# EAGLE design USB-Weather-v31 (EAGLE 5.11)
SFENUM: VREG-9872

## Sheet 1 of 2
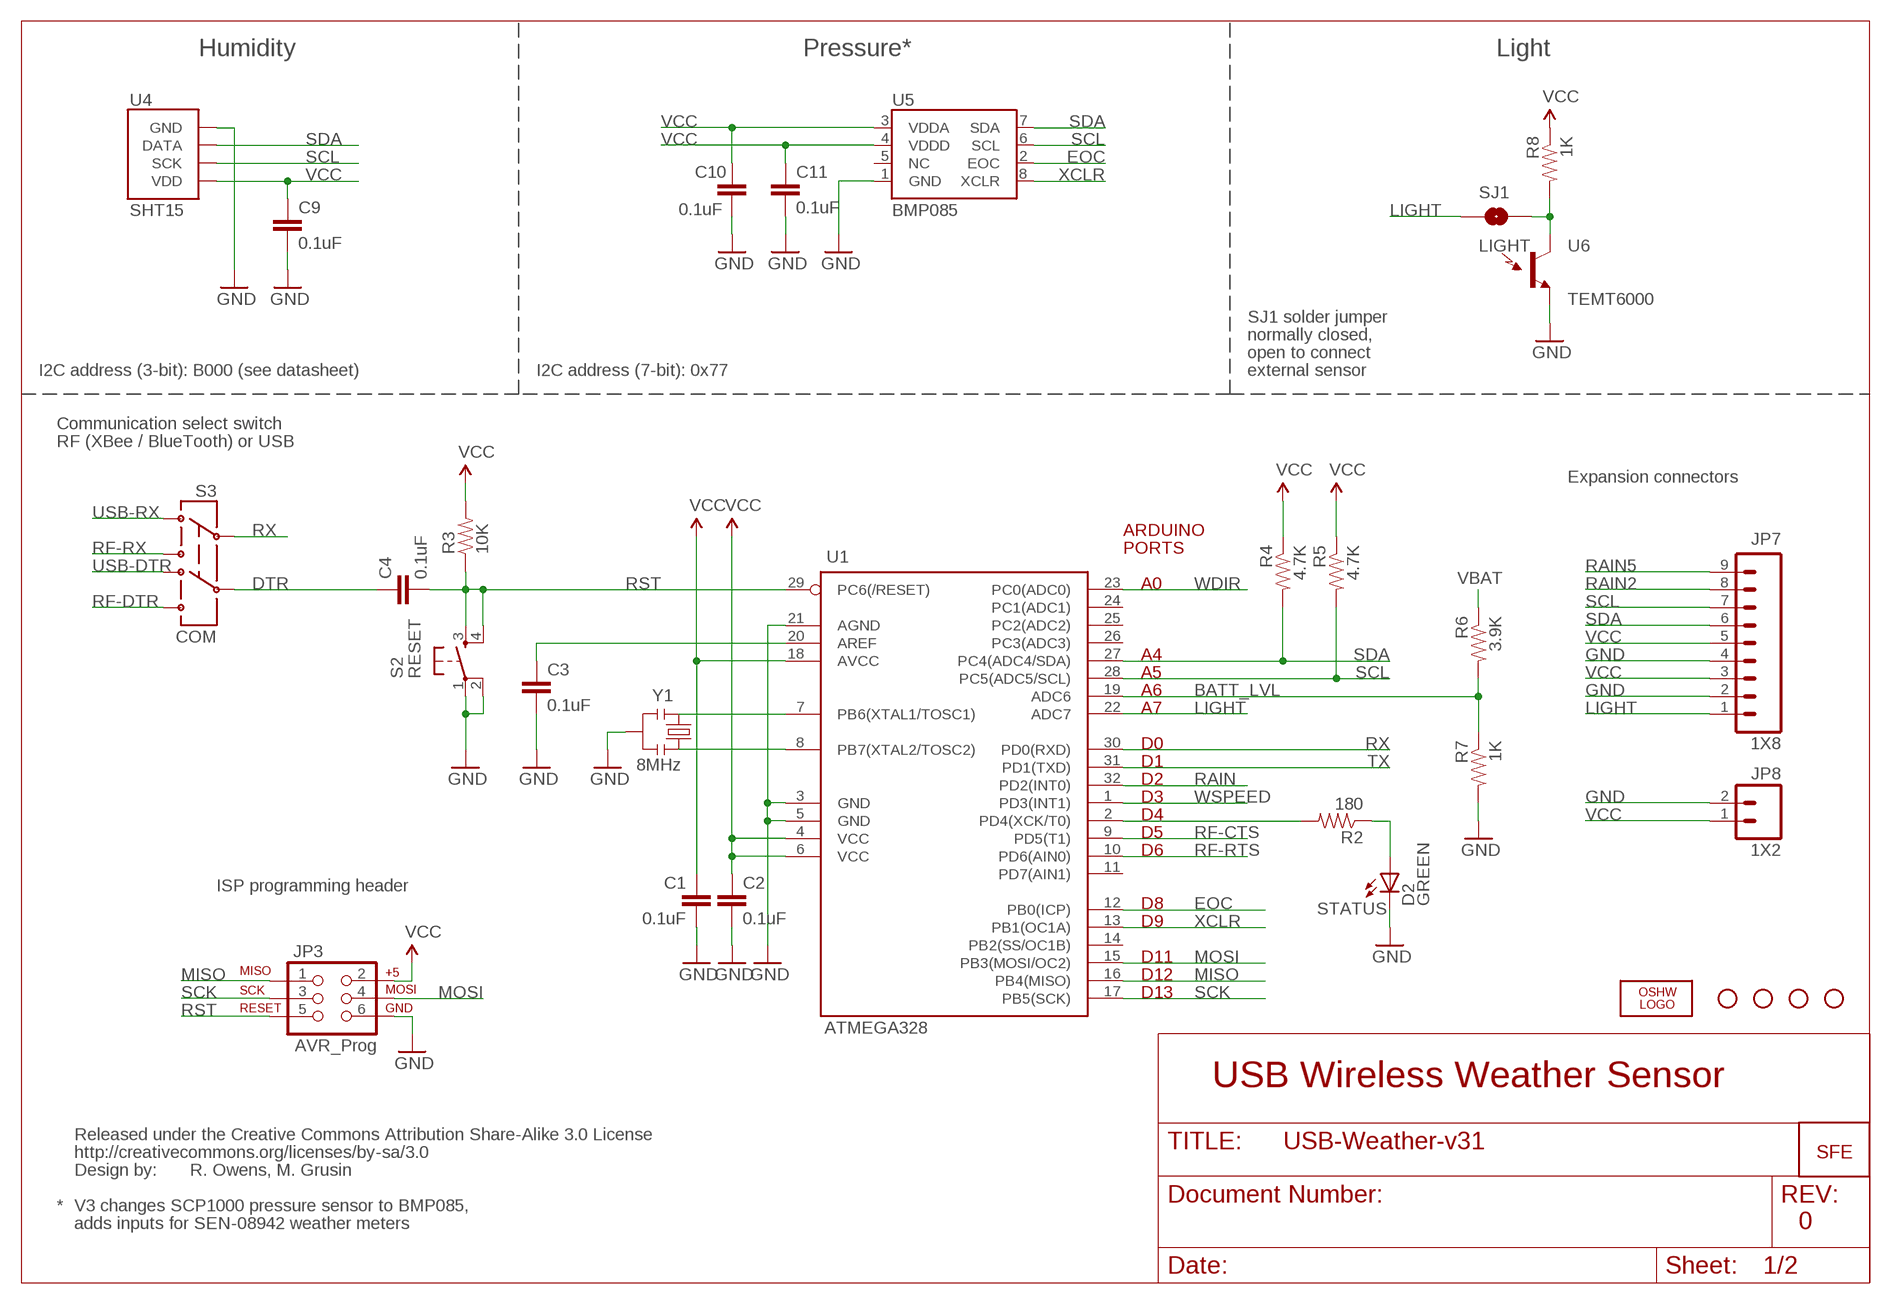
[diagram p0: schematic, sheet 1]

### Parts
C1  0.1uF  CAP0402-CAP  [0402-CAP]
C2  0.1uF  CAP0402-CAP  [0402-CAP]
C3  0.1uF  CAP0402-CAP  [0402-CAP]
C4  0.1uF  CAP0402-CAP  [0402-CAP]
C9  0.1uF  CAP0402-CAP  [0402-CAP]
C10  0.1uF  CAP0402-CAP  [0402-CAP]
C11  0.1uF  CAP0402-CAP  [0402-CAP]
D2  GREEN  LED0603  [LED-0603]
JP3  AVR_Prog  AVR_SPI_PRG_6PTH  [2X3]
JP7  1X8  M09  [1X09]
JP8  1X2  M02PTH  [1X02]
LOGO1  OSHW_LOGO_FILLX0100-NT  [OSHW_FILLX100_NOTEXT]
R2  180  RESISTOR0402-RES  [0402-RES]
R3  10K  RESISTOR0402-RES  [0402-RES]
R4  4.7K  RESISTOR0402-RES  [0402-RES]
R5  4.7K  RESISTOR0402-RES  [0402-RES]
R6  3.9K  RESISTOR0402-RES  [0402-RES]
R7  1K  RESISTOR0402-RES  [0402-RES]
R8  1K  RESISTOR0402-RES  [0402-RES]
S2  RESET  TAC_SWITCHSMD  [TACTILE_SWITCH_SMD]
S3  COM  SWITCH-DPDTSMD  [AYZ0202]
SJ1  LIGHT  SOLDERJUMPERNC  [SJ_2S]
U1  ATMEGA328  AVR-MEGA8-AI  [TQFP32-08]
U4  SHT15  SHT1XSMD  [SHT1X]
U5  BMP085  [BMP085]
U6  TEMT6000  [TEMT6000-SEN]
U$1  LOGO-SFENEW  [SFE-NEW-WEBLOGO]
U$2  STAND-OFF  [STAND-OFF]
U$3  STAND-OFF  [STAND-OFF]
U$4  STAND-OFF  [STAND-OFF]
U$5  STAND-OFF  [STAND-OFF]
U$6  CREATIVE_COMMONS  [CREATIVE_COMMONS]
Y1  8MHz  RESONATORSMD  [RESONATOR-SMD]

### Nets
BATT_LVL: R6.2 R7.1 U1.19(ADC6)
DTR: C4.1 S3.5
EOC: U1.12(PB0(ICP)) U5.2(EOC)
GND: C1.2 C2.2 C3.2 C9.2 C10.1 C11.2 D2.C JP3.6 JP7.2 JP7.4 JP8.2 R7.2 S2.1 S2.2 U1.3(GND) U1.5(GND) U1.21(AGND) U4.1(GND) U5.1(GND) U6.EMITTER(E1) Y1.2 ; also sheet 2
LIGHT: JP7.1 SJ1.1 U1.22(ADC7)
MISO: JP3.1 U1.16(PB4(MISO))
MOSI: JP3.4 U1.15(PB3(MOSI/OC2))
N$4: R2.2 U1.2(PD4(XCK/T0))
N$5: D2.A R2.1
N$8: C3.1 U1.20(AREF)
N$9: R8.2 SJ1.2 U6.COLLECTOR(C1)
N$10: U1.7(PB6(XTAL1/TOSC1)) Y1.1
N$14: U1.8(PB7(XTAL2/TOSC2)) Y1.3
RAIN: U1.32(PD2(INT0)) ; also sheet 2
RAIN2: JP7.8 ; also sheet 2
RAIN5: JP7.9 ; also sheet 2
RF-CTS: U1.9(PD5(T1)) ; also sheet 2
RF-DTR: S3.6 ; also sheet 2
RF-RTS: U1.10(PD6(AIN0)) ; also sheet 2
RF-RX: S3.3 ; also sheet 2
RST: C4.2 JP3.5 R3.1 S2.3 S2.4 U1.29(PC6(/RESET))
RX: S3.2 U1.30(PD0(RXD))
SCK: JP3.3 U1.17(PB5(SCK))
SCL: JP7.7 R5.2 U1.28(PC5(ADC5/SCL)) U4.3(SCK) U5.6(SCL)
SDA: JP7.6 R4.2 U1.27(PC4(ADC4/SDA)) U4.2(DATA) U5.7(SDA)
TX: U1.31(PD1(TXD)) ; also sheet 2
USB-DTR: S3.4 ; also sheet 2
USB-RX: S3.1 ; also sheet 2
VBAT: R6.1 ; also sheet 2
VCC: C1.1 C2.1 C9.1 C10.2 C11.1 JP3.2 JP7.3 JP7.5 JP8.1 R3.2 R4.1 R5.1 R8.1 U1.4(VCC) U1.6(VCC) U1.18(AVCC) U4.4(VDD) U5.3(VDDA) U5.4(VDDD) ; also sheet 2
WDIR: U1.23(PC0(ADC0)) ; also sheet 2
WSPEED: U1.1(PD3(INT1)) ; also sheet 2
XCLR: U1.13(PB1(OC1A)) U5.8(XCLR)
Unconnected: U1.11(PD7(AIN1)) U1.14(PB2(SS/OC1B)) U1.24(PC1(ADC1)) U1.25(PC2(ADC2)) U1.26(PC3(ADC3)) U5.5(NC)

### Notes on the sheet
- Humidity | Pressure* | Light
- SJ1 solder jumper
- normally closed,
- open to connect
- I2C address (3-bit): B000 (see datasheet) | I2C address (7-bit): 0x77 | external sensor
- Communication select switch
- RF (XBee / BlueTooth) or USB
- Expansion connectors
- ARDUINO
- PORTS
- A0
- A4
- A5
- A6
- A7
- D0
- D1
- D2
- D3
- D4
- D5
- D6
- ISP programming header
- D8
- STATUS
- D9
- D11
- D12
- D13
- USB Wireless Weather Sensor
- R. Owens, M. Grusin
- * | V3 changes SCP1000 pressure sensor to BMP085,
- adds inputs for SEN-08942 weather meters | 0

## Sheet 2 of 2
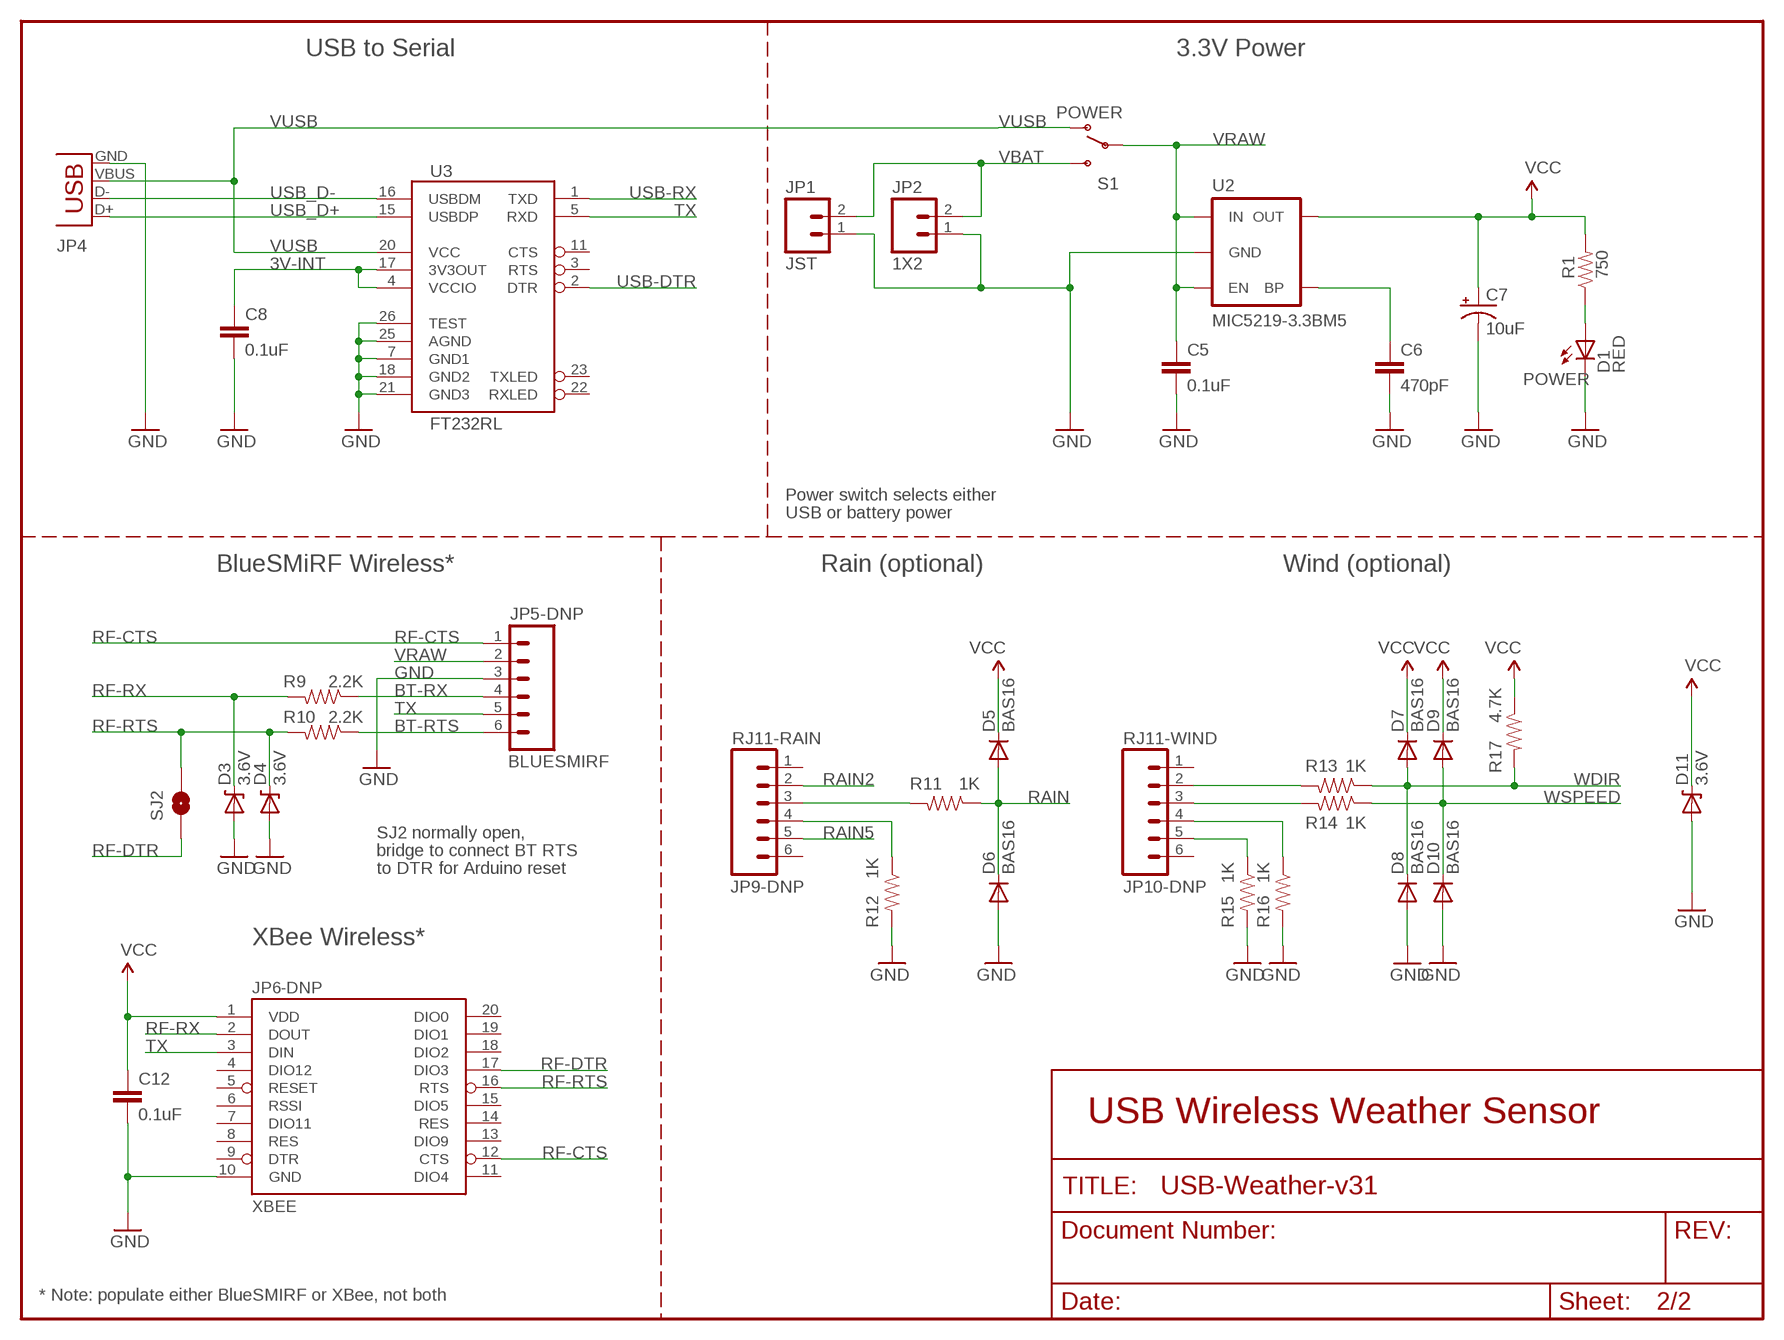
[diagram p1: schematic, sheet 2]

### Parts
C5  0.1uF  CAP0402-CAP  [0402-CAP]
C6  470pF  CAP0402-CAP  [0402-CAP]
C7  10uF  CAP_POL1206  [EIA3216]
C8  0.1uF  CAP0402-CAP  [0402-CAP]
C12  0.1uF  CAP0402-CAP  [0402-CAP]
D1  RED  LED0603  [LED-0603]
D3  3.6V  DIODE-ZENER-BZT52  [SOD-323]
D4  3.6V  DIODE-ZENER-BZT52  [SOD-323]
D5  BAS16  DIODESOD  [SOD-323]
D6  BAS16  DIODESOD  [SOD-323]
D7  BAS16  DIODESOD  [SOD-323]
D8  BAS16  DIODESOD  [SOD-323]
D9  BAS16  DIODESOD  [SOD-323]
D10  BAS16  DIODESOD  [SOD-323]
D11  3.6V  DIODE-ZENER-BZT52  [SOD-323]
JP1  JST  M02-JST-2MM-SMT  [JST-2-SMD]
JP2  1X2  M021X02_NO_SILK  [1X02_NO_SILK]
JP4  USBSMD  [USB-MINIB]
JP5-DNP  BLUESMIRF  M06SIP  [1X06]
JP6-DNP  XBEE  XBEE-1B1  [XBEE-1]
JP9-DNP  RJ11-RAIN  RJ11-6PTH  [RJ11-6]
JP10-DNP  RJ11-WIND  RJ11-6PTH  [RJ11-6]
R1  750  RESISTOR0402-RES  [0402-RES]
R9  2.2K  RESISTOR0402-RES  [0402-RES]
R10  2.2K  RESISTOR0402-RES  [0402-RES]
R11  1K  RESISTOR0402-RES  [0402-RES]
R12  1K  RESISTOR0402-RES  [0402-RES]
R13  1K  RESISTOR0402-RES  [0402-RES]
R14  1K  RESISTOR0402-RES  [0402-RES]
R15  1K  RESISTOR0402-RES  [0402-RES]
R16  1K  RESISTOR0402-RES  [0402-RES]
R17  4.7K  RESISTOR0402-RES  [0402-RES]
S1  POWER  SWITCH-SPSTSMD  [AYZ0202]
SJ2  SOLDERJUMPERNO  [SJ_2S-NO]
U2  MIC5219-3.3BM5  V_REG_LDOSMD  [SOT23-5]
U3  FT232RL  FT232RL-BASICSSOP  [SSOP28DB]

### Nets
3V-INT: C8.1 U3.4(VCCIO) U3.17(3V3OUT)
BT-RTS: JP5-DNP.6 R10.1
BT-RX: JP5-DNP.4 R9.1
GND: C5.2 C6.2 C7.C(-) C8.2 C12.2 D1.C D3.2(A) D4.2(A) D6.2(A) D8.2(A) D10.2(A) D11.2(A) JP1.1 JP2.1 JP4.GND JP5-DNP.3 JP6-DNP.10(GND) R12.2 R15.2 R16.2 U2.2(GND) U3.7(GND1) U3.18(GND2) U3.21(GND3) U3.25(AGND) U3.26(TEST) ; also sheet 1
N$1: D1.A R1.1
N$2: JP10-DNP.2 R13.2
N$3: JP10-DNP.3 R14.2
N$6: C6.1 U2.4(BP)
N$7: JP9-DNP.3 R11.2
N$11: JP9-DNP.4 R12.1
N$12: JP10-DNP.5 R15.1
N$13: JP10-DNP.4 R16.1
RAIN: D5.2(A) D6.1(C) R11.1 ; also sheet 1
RAIN2: JP9-DNP.2 ; also sheet 1
RAIN5: JP9-DNP.5 ; also sheet 1
RF-CTS: JP5-DNP.1 JP6-DNP.12(CTS) ; also sheet 1
RF-DTR: JP6-DNP.17(DIO3) SJ2.1 ; also sheet 1
RF-RTS: D4.1(C) JP6-DNP.16(RTS) R10.2 SJ2.2 ; also sheet 1
RF-RX: D3.1(C) JP6-DNP.2(DOUT) R9.2 ; also sheet 1
TX: JP5-DNP.5 JP6-DNP.3(DIN) U3.5(RXD) ; also sheet 1
USB-DTR: U3.2(DTR) ; also sheet 1
USB-RX: U3.1(TXD) ; also sheet 1
USB_D+: JP4.D+ U3.15(USBDP)
USB_D-: JP4.D- U3.16(USBDM)
VBAT: JP1.2 JP2.2 S1.3(S) ; also sheet 1
VCC: C7.A(+) C12.1 D5.1(C) D7.1(C) D9.1(C) D11.1(C) JP6-DNP.1(VDD) R1.2 R17.1 U2.5(OUT) ; also sheet 1
VRAW: C5.1 JP5-DNP.2 S1.2(P) U2.1(IN) U2.3(EN)
VUSB: JP4.VBUS S1.1(O) U3.20(VCC)
WDIR: D7.2(A) D8.1(C) R13.1 R17.2 ; also sheet 1
WSPEED: D9.2(A) D10.1(C) R14.1 ; also sheet 1
Unconnected: JP6-DNP.4(DIO12) JP6-DNP.5(RESET) JP6-DNP.6(RSSI) JP6-DNP.7(DIO11) JP6-DNP.8(RES) JP6-DNP.9(DTR) JP6-DNP.11(DIO4) JP6-DNP.13(DIO9) JP6-DNP.14(RES) JP6-DNP.15(DIO5) JP6-DNP.18(DIO2) JP6-DNP.19(DIO1) JP6-DNP.20(DIO0) JP9-DNP.1 JP9-DNP.6 JP10-DNP.1 JP10-DNP.6 U3.3(RTS) U3.11(CTS) U3.22(RXLED) U3.23(TXLED)

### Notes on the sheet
- USB to Serial | 3.3V Power
- JP4
- POWER
- Power switch selects either
- USB or battery power
- Rain (optional) | Wind (optional)
- BlueSMiRF Wireless*
- SJ2 normally open,
- bridge to connect BT RTS
- to DTR for Arduino reset
- XBee Wireless*
- USB Wireless Weather Sensor
- * Note: populate either BlueSMIRF or XBee, not both

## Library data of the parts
C1-C6 C8-C12 = SparkFun:CAP: Capacitor
C7 = SparkFun:CAP_POL: Capacitor Polarized
D1 D2 = SparkFun:LED: LEDs
D3 D4 D11 = SparkFun:DIODE-ZENER: Zener Diode
D5-D10 = SparkFun:DIODE: Diode
JP1 JP2 JP8 = SparkFun:M02: Header 2
JP3 = SparkFun:AVR_SPI_PRG_6: AVR ISP 6 Pin This is the reduced ISP connector for AVR programming. Common on Arduino. This footprint will take up less PCB space and can be used with a 10-pin to 6-pin adapter such as SKU: BOB-08508
JP4 = SparkFun:USB: USB Connectors USB-B-PTH is fully proven SKU : PRT-00139 USB-miniB is fully proven SKU : PRT-00587 USB-A-PCB is untested. USB-A-H is throughly reviewed, but untested. Spark Fun Electronics SKU : PRT-00437 USB-B-SMT is throughly reviewed, but untested. Needs silkscreen touching up. USB-A-S has not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
JP5-DNP = SparkFun:M06: Header 6 Standard 6-pin 0.1" header. Use with straight break away headers (SKU : PRT-00116), right angle break away headers (PRT-00553), swiss pins (PRT-00743), machine pins (PRT-00117), and female headers (PRT-00115). Molex polarized connector foot print use with SKU : PRT-08094 with associated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
JP6-DNP = SparkFun:XBEE-1
JP7 = SparkFun:M09: Header 9 Standard 9-pin 0.1" header. Use with straight break away headers (SKU : PRT-00116), right angle break away headers (PRT-00553), swiss pins (PRT-00743), machine pins (PRT-00117), and female headers (PRT-00115).
JP9-DNP JP10-DNP = SparkFun:RJ11-6: RJ11 Jack Simple 6 pin RJ11 jack. Commonly found on CAT3 devices and Microchip programmers. SKU: PRT-00132
LOGO1 = OSHW:OSHW_LOGO_FILL
R1-R17 = SparkFun:RESISTOR: Resistor
S1 = SparkFun:SWITCH-SPST: SPST Switch Simple slide switch. Spark Fun Electronics SKU : COM-00102
S2 = SparkFun:TAC_SWITCH: Momentary Switch Button commonly used for reset or general input. Spark Fun Electronics SKU : COM-00097
S3 = SparkFun:SWITCH-DPDT: DPDT Version of the COM-00597
SJ1 SJ2 = SparkFun:SOLDERJUMPER: Solder Jumper
U1 = SparkFun:AVR-MEGA8: MICROCONTROLLER 8 Kbytes FLASH 1 kbytes SRAM 512 bytes EEPROM USART 6-channel 10 bit ADC 2-channel 8 bit ADC
U2 = SparkFun:V_REG_LDO: Voltage Regulator LDO Standard 150mA LDO voltage regulator in SOT-23 layout. Micrel part MIC5205. BP (by-pass) pin is used to lower output noise with 470pF cap.
U3 = SparkFun:FT232RL-BASIC: USB UART This is the simplified version of the FT232RL unit. Only what you need, nothing you don't. Spark Fun Electronics SKU : COM-00650
U4 = SparkFun:SHT1X: SHT1x Humdity Sensor Sensirion humdity sensor. Schematic element and footprint proven. Spark Fun Electronics SKU : COM-08227
U5 = SparkFun:BMP085: BMP085 Pressure Sensor Great little MEMS pressure sensor. SKU: COM-09603
U6 = SparkFun:TEMT6000: Ambient Light Sensor
U$1 = SparkFun:LOGO-SFE: Spark Fun Electronics PCB Logo
U$2-U$5 = SparkFun:STAND-OFF: Stand Off
U$6 = SparkFun:CREATIVE_COMMONS
Y1 = SparkFun:RESONATOR: Resonator Small SMD resonator. This is the itty bitty 10/20MHz resonators with built in caps. CSTCE10M0G55 and CSTCE20M0V53. Footprint has been reviewed closely but hasn't been tested yet.

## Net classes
0 Default: width 0.203 mm
1 Power: width 0.305 mm

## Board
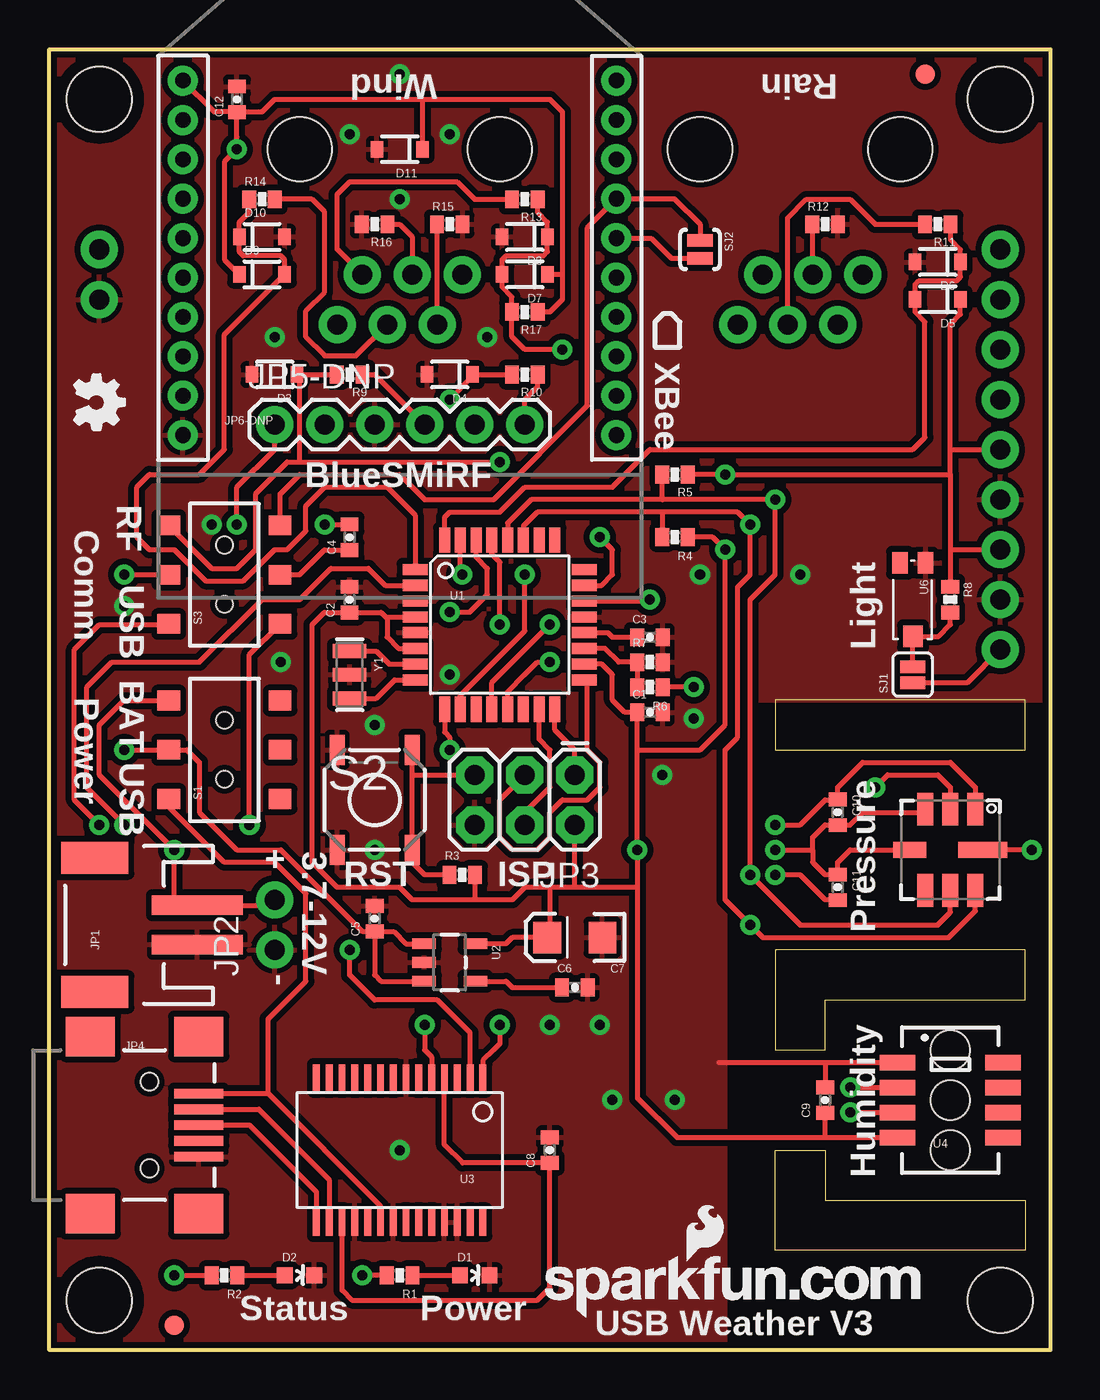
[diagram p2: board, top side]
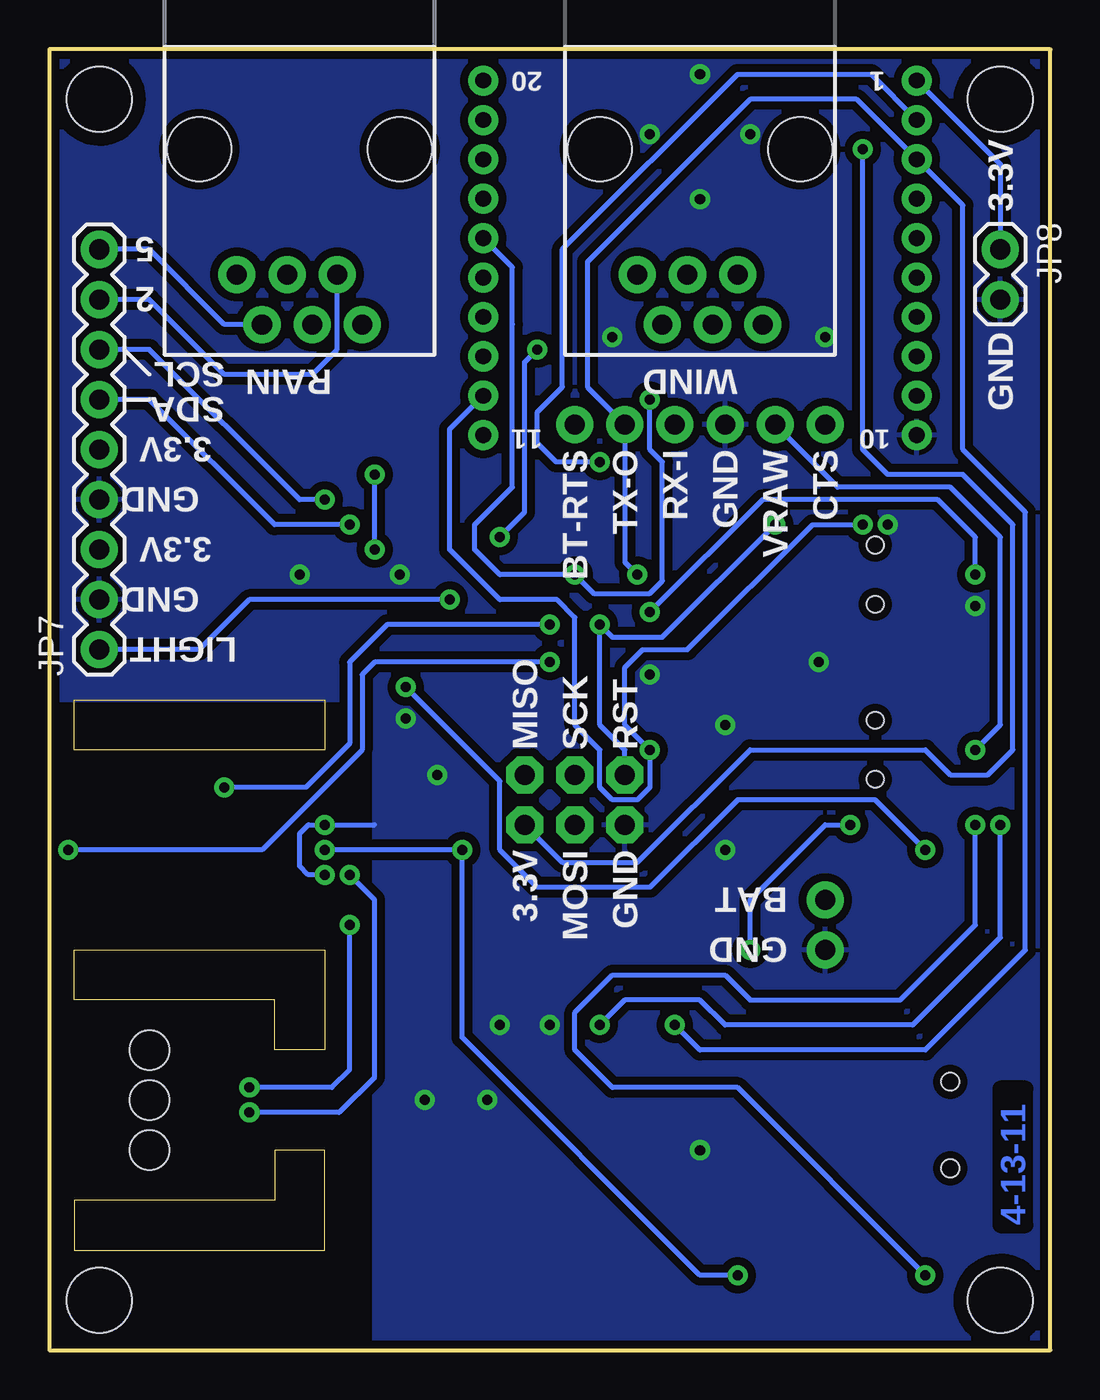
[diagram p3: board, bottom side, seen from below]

Size 50.8 x 66.04 mm. Coordinates in mm from the lower left corner, seen from the top.
Outline: 0,66.04 50.8,66.04 50.8,0 0,0 0,66.04
Copper layers (1*16): Top 0.035mm / dielectric 1.5mm / Bottom 0.035mm
Design rules "SparkFun *": minimum track width 8mil, minimum drill 20mil, track to track 8mil, track to pad 8mil, pad to pad 8mil, via to via 8mil, smd to smd 8mil, copper to edge 8mil, drill to drill 8mil, minimum pad ring 12mil, minimum via ring 10mil, stop-mask expansion 4mil, vias tented up to drill 20mil, thermal gap 10mil
Holes 2 mm at 45.72,15.24 45.72,12.7 45.72,10.16
Milling: area 36.8,15.2 to 49.5,20.3; area 36.8,5.1 to 49.5,10.2; area 36.8,30.5 to 49.5,33

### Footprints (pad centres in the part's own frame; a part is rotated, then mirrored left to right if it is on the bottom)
0402-CAP = smd 0.7 x 0.9: 1 -0.65,0; 2 0.65,0
EIA3216 = smd 1.4 x 1.6: A 1.4,0; C -1.4,0
LED-0603 = smd 0.8 x 0.8: A 0,-0.75; C 0,0.75
SOD-323 = smd 0.63 x 0.83: 1 -1.15,0; 2 1.15,0
FIDUCIAL-1X2 = smd 1 x 1: 1 0,0
JST-2-SMD = smd 1 x 4.6: 1 -1,-3.7; 2 1,-3.7 | smd 1.6 x 3.4: NC1 -3.4,1.5; NC2 3.4,1.5
1X02_NO_SILK = drill 1.016 pad 1.88 round: 1 0,0; 2 2.54,0
2X3 = drill 1.016 pad 1.88 octagon: 1 0,0; 2 0,2.54; 3 2.54,0; 4 2.54,2.54; 5 5.08,0; 6 5.08,2.54
USB-MINIB = smd 2.5 x 0.5: D+ 2.5,0; D- 2.5,0.8; GND 2.5,-1.6; ID 2.5,-0.8; VBUS 2.5,1.6 | smd 2.5 x 2: MTN1 -3,4.5; MTN2 2.5,4.5; MTN3 -3,-4.5; MTN4 2.5,-4.5 | hole 0.9: 0,2.2; 0,-2.2
1X06 = drill 1.016 pad 1.88 round: 1 0,0; 2 2.54,0; 3 5.08,0; 4 7.62,0; 5 10.16,0; 6 12.7,0
XBEE-1 = drill 0.8 pad 1.524 round: 1 -11,20; 2 -11,18; 3 -11,16; 4 -11,14; 5 -11,12; 6 -11,10; 7 -11,8; 8 -11,6; 9 -11,4; 10 -11,2; 11 11,2; 12 11,4; 13 11,6; 14 11,8; 15 11,10; 16 11,12; 17 11,14; 18 11,16; 19 11,18; 20 11,20
1X09 = drill 1.016 pad 1.88 round: 1 0,0; 2 2.54,0; 3 5.08,0; 4 7.62,0; 5 10.16,0; 6 12.7,0; 7 15.24,0; 8 17.78,0; 9 20.32,0
1X02 = drill 1.016 pad 1.88 round: 1 0,0; 2 2.54,0
RJ11-6 = drill 1.016 pad 1.88 round: 1 1.905,8.89; 2 3.175,6.35; 3 4.445,8.89; 4 5.715,6.35; 5 6.985,8.89; 6 8.255,6.35 | hole 3.251: 0,0; 10.16,0
0402-RES = smd 0.7 x 0.9: 1 -0.65,0; 2 0.65,0
AYZ0202 = smd 1 x 1.15: 1 -2.5,2.825; 2 0,2.825; 3 2.5,2.825; 4 -2.5,-2.825; 5 0,-2.825; 6 2.5,-2.825 | hole 0.85: 1.5,0; -1.5,0
TACTILE_SWITCH_SMD = smd 1.524 x 0.762: 1 -2.54,1.905; 2 2.54,1.905; 3 -2.54,-1.905; 4 2.54,-1.905
SJ_2S = smd 0.635 x 1.27: 1 -0.412,0; 2 0.412,0
SJ_2S-NO = smd 0.635 x 1.27: 1 -0.45,0; 2 0.45,0
TQFP32-08 = smd 1.27 x 0.559: 1 -4.293,2.8; 2 -4.293,2; 3 -4.293,1.2; 4 -4.293,0.4; 5 -4.293,-0.4; 6 -4.293,-1.2; 7 -4.293,-2; 8 -4.293,-2.8; 17 4.293,-2.8; 18 4.293,-2; 19 4.293,-1.2; 20 4.293,-0.4; 21 4.293,0.4; 22 4.293,1.2; 23 4.293,2; 24 4.293,2.8 | smd 0.559 x 1.27: 9 -2.8,-4.293; 10 -2,-4.293; 11 -1.2,-4.293; 12 -0.4,-4.293; 13 0.4,-4.293; 14 1.2,-4.293; 15 2,-4.293; 16 2.8,-4.293; 25 2.8,4.293; 26 2,4.293; 27 1.2,4.293; 28 0.4,4.293; 29 -0.4,4.293; 30 -1.2,4.293; 31 -2,4.293; 32 -2.8,4.293
SOT23-5 = smd 0.55 x 1.2: 1 -0.95,-1.3; 2 0,-1.3; 3 0.95,-1.3; 4 0.95,1.3; 5 -0.95,1.3
SSOP28DB = smd 0.348 x 1.397: 1 -4.225,-3.656; 2 -3.575,-3.656; 3 -2.925,-3.656; 4 -2.275,-3.656; 5 -1.625,-3.656; 6 -0.975,-3.656; 7 -0.325,-3.656; 8 0.325,-3.656; 9 0.975,-3.656; 10 1.625,-3.656; 11 2.275,-3.656; 12 2.925,-3.656; 13 3.575,-3.656; 14 4.225,-3.656; 15 4.225,3.656; 16 3.575,3.656; 17 2.925,3.656; 18 2.275,3.656; 19 1.625,3.656; 20 0.975,3.656; 21 0.325,3.656; 22 -0.325,3.656; 23 -0.975,3.656; 24 -1.625,3.656; 25 -2.275,3.656; 26 -2.925,3.656; 27 -3.575,3.656; 28 -4.225,3.656
SHT1X = smd 1.8 x 0.8: 1 -2.667,1.905; 2 -2.667,0.635; 3 -2.667,-0.635; 4 -2.667,-1.905; 5 2.667,-1.905; 6 2.667,-0.635; 7 2.667,0.635; 8 2.667,1.905
BMP085 = smd 1.67 x 0.8: 1 -2.065,1.27; 2 -2.065,0; 3 -2.065,-1.27; 5 2.065,-1.27; 6 2.065,0; 7 2.065,1.27 | smd 0.8 x 1.67: 4 0,-2.065 | smd 0.8 x 2.5: 8 0,1.65
TEMT6000-SEN = smd 1.1 x 0.8: BASE -1.87,-0.65; EMITTER -1.87,0.65 | smd 1.1 x 1: COLLECTOR 1.86,0.01
STAND-OFF = hole 3.302: 0,0
RESONATOR-SMD = smd 0.7 x 1.7: 1 -1.2,0; 2 0,0; 3 1.2,0

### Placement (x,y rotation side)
C1  30.48,32.38 0 top
C2  15.24,38.1 90 top
C3  30.48,36.2 0 top
C4  15.24,41.27 90 top
C5  16.51,21.91 90 top
C6  26.67,18.41 0 top
C7  26.67,20.95 180 top
C8  25.4,10.16 90 top
C9  39.37,12.7 90 top
C10  40.01,27.3 270 top
C11  40.01,23.5 270 top
C12  9.53,63.5 90 top
D1  21.59,3.81 270 top
D2  12.7,3.81 270 top
D3  11.43,49.53 180 top
D4  20.32,49.53 180 top
D5  45.09,53.34 180 top
D6  45.09,55.24 180 top
D7  24.13,54.61 180 top
D8  24.13,56.52 180 top
D9  10.79,54.61 0 top
D10  10.79,56.52 0 top
D11  17.78,60.96 180 top
E$1  [FIDUCIAL-1X2]  44.45,64.77 0 top
E$2  [FIDUCIAL-1X2]  6.35,1.27 0 top
JP1  3.81,21.59 90 top
JP2  11.43,20.32 90 top
JP3  26.67,29.21 180 top
JP4  5.08,11.43 0 top
JP5-DNP  11.43,46.99 0 top
JP6-DNP  17.78,44.45 0 top
JP7  48.26,35.56 90 bottom
JP8  2.54,55.88 270 bottom
JP9-DNP  33.02,60.96 180 bottom
JP10-DNP  12.7,60.96 180 bottom
LOGO1  1.27,49.53 270 top
R1  17.78,3.81 180 top
R2  8.89,3.81 180 top
R3  20.95,24.13 0 top
R4  31.75,41.27 180 top
R5  31.75,44.45 180 top
R6  30.48,33.66 180 top
R7  30.48,34.92 0 top
R8  45.72,38.1 270 top
R9  15.24,49.53 180 top
R10  24.13,49.53 180 top
R11  45.09,57.15 180 top
R12  39.37,57.15 0 top
R13  24.13,58.42 180 top
R14  10.79,58.42 0 top
R15  20.32,57.15 0 top
R16  16.51,57.15 180 top
R17  24.13,52.7 180 top
S1  8.89,30.48 90 top
S2  16.51,27.94 90 top
S3  8.89,39.37 90 top
SJ1  43.81,34.29 90 top
SJ2  33.02,55.88 270 top
U1  22.86,36.83 0 top
U2  20.32,19.68 270 top
U3  17.78,10.16 180 top
U4  45.72,12.7 0 top
U5  45.72,25.4 270 top
U6  43.81,38.1 270 top
U$1  25.15,1.65 0 top
U$2  2.54,2.54 0 top
U$3  48.26,2.54 0 top
U$4  2.54,63.5 0 top
U$5  48.26,63.5 0 top
U$6  not placed on the board
Y1  15.24,34.29 270 top

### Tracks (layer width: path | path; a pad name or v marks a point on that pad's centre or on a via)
3V-INT
  Top 0.254: U3.17 14.86,3.04 15.35,2.54 24.77,2.54 25.4,3.17 C8.1 20.97,9.51 20.05,10.43 U3.4
BATT_LVL
  Top 0.254: U1.19 28.19,35.63 28.89,34.92 R7.1 29.84,34.92 R7.1 R6.2
BT-RTS
  Top 0.254: R10.1 24.78,48.91 24.13,48.26 JP5-DNP.6
BT-RX
  Top 0.254: R9.1 16.51,49.53 JP5-DNP.4
DTR
  Top 0.254: S3.5 12.7,39.37 13.96,40.62 C4.1
EOC  (via drill 0.51)
  Top 0.254: U5.2 45.72,28.57 45.09,29.21 42.55,29.21 v41.91,28.57 | U1.12 22.46,33.89 v25.4,36.83
  Bottom 0.254: v25.4,36.83 33.66,36.83 35.56,34.92 35.56,30.8 37.78,28.57 v41.91,28.57
GND  (via drill 0.51)
  Top 0.254: U5.1 46.99,28.57 45.72,29.84 41.27,29.84 40.01,28.57 C10.1 39.37,27.94 38.1,26.67 v36.83,26.67 | C11.2 39.99,22.86 39.37,22.86 38.1,24.13 v36.83,24.13 | 39.37,14.61 U4.1 | 33.97,14.61 39.37,14.61 | 39.37,14.61 C9.2
  Bottom 0.254: 34.29,26.67 v36.83,26.67 37.65,26.67 38.1,26.22 38.1,24.58 37.65,24.13 v36.83,24.13
  other vias: 16.51,31.75 11.43,51.44 20.32,61.72 32.7,32.07 25.4,16.51 16.51,25.4 17.78,10.16 28.57,12.7 20.32,34.29 27.94,16.51 3.81,37.78 31.11,29.21 38.1,39.37 33.02,39.37 15.24,61.72 22.23,51.44 17.78,58.42 17.78,64.77 8.26,41.91 31.75,12.7 11.75,34.92
  pour Bottom (isolate 0.406): 34.29,0 34.29,33.02 50.8,33.02 50.8,66.04 0,66.04 0,0
  pour Top (isolate 0.305): 34.29,0 34.29,33.02 50.8,33.02 50.8,66.04 0,66.04 0,0
LIGHT  (via drill 0.51)
  Top 0.254: U1.22 30.41,38.03 v30.48,38.1 | SJ1.1 46.58,33.88 JP7.1
  Bottom 0.254: v30.48,38.1 40.64,38.1 43.18,35.56 JP7.1
MISO
  Top 0.254: U1.16 25.66,31.49 26.67,30.48 JP3.1
MOSI
  Top 0.254: JP3.4 24.13,27.3 25.4,28.57 25.4,30.48 24.86,31.02 U1.15
N$1
  Top 0.254: R1.1 D1.A
N$2
  Top 0.254: JP10-DNP.2 14.61,55.88 14.61,56.01 14.61,58.67 15.24,59.31 20.7,59.31 21.59,58.42 R13.2
N$3
  Top 0.254: R14.2 11.43,58.41 | JP10-DNP.3 15.56,50.48 13.97,50.48 13.02,51.44 13.02,52.77 13.97,53.72 13.97,57.78 13.34,58.42 R14.2 | R14.2 11.43,58.42
N$4  (via drill 0.51)
  Top 0.254: U1.2 17.05,38.83 16.19,39.69 14.29,39.69 12.7,38.1 10.79,38.1 7.62,34.92 3.17,34.92 1.91,33.66 1.91,28.57 v3.81,26.67 | 8.26,3.81 R2.2 v6.35,3.81
  Bottom 0.254: v6.35,3.81 15.88,13.34 22.23,13.34 24.13,15.24 24.13,17.14 22.23,19.05 16.51,19.05 15.24,17.78 7.62,17.78 3.81,21.59 v3.81,26.67
N$5
  Top 0.254: R2.1 D2.A
N$6
  Top 0.254: U2.4 23.18,18.73 23.5,18.41 C6.1
N$7
  Top 0.254: JP9-DNP.3 37.47,57.47 38.42,58.42 40.64,58.42 41.91,57.15 R11.2
N$8
  Top 0.254: U1.20 28.34,36.43 28.57,36.2 C3.1
N$9
  Top 0.254: SJ1.2 43.83,34.71 U6.COLLECTOR 45.13,36.24 45.72,36.83 R8.2
N$10
  Top 0.254: U1.7 17.24,34.83 16.58,35.49 Y1.1
N$11
  Top 0.254: JP9-DNP.4 38.73,57.13 R12.1
N$12
  Top 0.254: JP10-DNP.5 19.68,57.15 R15.1
N$13
  Top 0.254: R16.1 17.78,57.15 18.41,56.52 JP10-DNP.4
N$14
  Top 0.254: U1.8 17.52,34.03 16.58,33.09 Y1.3
RAIN
  Top 0.254: U1.32 20.06,42.28 20.32,42.55 22.86,42.55 24.13,43.81 28.57,43.81 30.48,45.72 43.81,45.72 44.44,46.34 44.44,52.21 43.94,52.71 D5.2 43.94,54.09 44.13,54.29 46.04,54.29 46.23,54.48 D6.1 46.23,55.87 45.73,56.37 R11.1 45.72,57.13
RAIN2
  Bottom 0.254: JP9-DNP.2 36.2,50.8 37.47,49.53 41.91,49.53 45.72,53.34 JP7.8
RAIN5
  Bottom 0.254: JP9-DNP.5 41.91,52.07 45.72,55.88 JP7.9
RF-CTS  (via drill 0.51)
  Top 0.254: JP5-DNP.1 11.43,45.72 9.53,43.81 v9.53,41.91 | U1.9 20.06,31.38 20.32,31.11 v20.32,30.48
  Bottom 0.254: v9.53,41.91 12.06,41.91 18.41,35.56 20.69,35.56 21.59,34.66 21.59,31.75 v20.32,30.48 20.32,28.57 20.95,27.94 22.23,27.94 22.86,28.57 22.86,30.48 24.13,31.75 24.13,37.2 25.03,38.1 27.94,38.1 30.48,40.64 30.48,46.75 JP6-DNP.12
RF-DTR
  Top 0.254: S3.6 11.71,43.47 12.7,44.45 17.78,44.45 19.05,43.18 22.54,43.18 27.3,47.94 27.3,56.98 JP6-DNP.17 31.72,58.45 33.02,57.15 SJ2.1
RF-RTS  (via drill 0.51)
  Top 0.254: R10.2 D4.1 21.47,49.41 v20.32,48.26 | v24.13,39.37 24.13,36.51 20.86,33.24 U1.10 | SJ2.2 31.57,55.43 31.11,55.88 30.55,56.45 JP6-DNP.16
  Bottom 0.254: v20.32,48.26 20.32,45.72 19.68,45.09 19.68,39.05 20.32,38.42 23.18,38.42 v24.13,39.37 27.94,39.37 29.21,40.64 29.21,41.91 27.3,43.81 27.3,52.07 27.3,54.98 JP6-DNP.16
RF-RX  (via drill 0.51)
  Top 0.254: 12.7,45.09 12.06,45.09 10.48,43.5 10.48,40.64 9.53,39.69 8.26,39.69 S3.3 | 12.7,45.09 v22.86,45.09 | 12.7,45.09 12.7,49.53 D3.1 R9.2
  Bottom 0.254: JP6-DNP.2 9.1,64.77 15.88,64.77 24.77,55.88 24.77,48.9 26.04,47.62 26.04,46.04 25.08,45.09 v22.86,45.09
RST  (via drill 0.51)
  Top 0.254: S2.3 18.4,25.39 | S2.3 18.41,27.3 18.41,29.21 | 18.41,29.21 S2.4 | S2.3 18.41,24.78 18.41,24.77 19.05,24.13 R3.1 | U1.29 22.46,40.41 22.86,40.01 v22.86,36.83 | C4.2 15.22,41.91 v13.97,41.91 | 18.41,29.21 JP3.5
  Bottom 0.254: JP3.5 21.59,30.48 22.86,31.75 v22.86,36.83 22.23,36.2 19.68,36.2 v13.97,41.91
RX  (via drill 0.51)
  Top 0.254: 6.35,39.37 S3.2 v3.81,39.37 | U1.30 21.66,40.25 22.23,39.69 22.23,38.36 21.33,37.47 v20.32,37.47
  Bottom 0.254: v3.81,39.37 3.81,41.27 5.71,43.18 14.61,43.18 v20.32,37.47
SCK
  Top 0.254: JP3.3 22.86,27.94 22.86,26.04 23.5,25.4 24.77,25.4 25.4,26.04 25.4,27.3 26.04,27.94 27.3,27.94 27.94,28.57 27.94,29.84 27.3,30.48 27.3,34.04 27.3,34.03 U1.17
SCL  (via drill 0.51)
  Top 0.254: 45.72,23.5 U5.6 45.72,22.23 45.09,21.59 38.1,21.59 v35.56,24.13 35.56,38.1 36.83,39.37 v36.83,43.18 31.11,43.18 | 31.11,43.18 31.11,44.45 R5.2 | 31.11,43.18 24.45,43.18 23.26,41.99 U1.28 | v40.64,12.06 U4.3
  Bottom 0.254: v35.56,24.13 34.29,22.86 34.29,13.86 36.09,12.06 v40.64,12.06 | v36.83,43.18 38.1,43.18 45.72,50.8 JP7.7
SDA  (via drill 0.51)
  Top 0.254: 46.99,23.5 U5.7 46.99,22.3 45.65,20.95 36.2,20.95 v35.56,21.59 34.29,22.86 34.29,30.48 34.92,31.11 34.92,38.73 35.56,39.37 v35.56,41.91 34.92,42.55 31.11,42.55 | 31.11,42.55 24.77,42.55 24.06,41.84 U1.27 | 31.11,42.55 31.11,41.27 R4.2 | v40.64,13.34 U4.2
  Bottom 0.254: v40.64,13.34 36.46,13.34 35.56,14.23 v35.56,21.59 | v35.56,41.91 39.37,41.91 45.72,48.26 JP7.6
TX  (via drill 0.51)
  Top 0.254: U1.31 20.86,39.47 v20.95,39.37 | U3.5 19.41,14.88 19.05,15.24 v19.05,16.51
  Bottom 0.254: v19.05,16.51 17.78,15.24 6.35,15.24 1.27,20.32 1.27,42.55 4.45,45.72 4.45,58.12 JP6-DNP.3 9.83,63.5 15.24,63.5 23.5,55.24 23.5,48.9 JP5-DNP.5 21.59,40.01 v20.95,39.37
USB-DTR  (via drill 0.51)
  Top 0.254: S3.4 10.16,35.31 v10.16,26.67 | v15.24,20.32 15.24,19.05 16.51,17.78 19.68,17.78 21.36,16.11 U3.2
  Bottom 0.254: v15.24,20.32 15.24,22.86 11.43,26.67 v10.16,26.67
USB-RX  (via drill 0.51)
  Top 0.254: 6.03,36.84 S3.1 6.03,36.83 2.54,36.83 1.27,35.56 1.27,27.94 v2.54,26.67 | U3.1 22,14.7 22.54,15.24 22.86,15.56 v22.86,16.51
  Bottom 0.254: v22.86,16.51 21.59,17.78 17.78,17.78 16.51,16.51 6.99,16.51 2.54,20.95 v2.54,26.67
USB_D+
  Top 0.254: U3.15 13.55,8.04 10.16,11.43 JP4.D+
USB_D-
  Top 0.254: U3.16 14.21,8.65 10.63,12.23 JP4.D-
VBAT  (via drill 0.51)
  Top 0.254: v32.7,33.66 R6.1 | JP2.2 11.16,22.59 JP1.2 6.62,22.59 6.35,22.86 v6.35,25.4 2.54,29.21 2.54,31.75 3.77,32.98 S1.3
  Bottom 0.254: v32.7,33.66 27.94,28.89 27.94,25.4 26.04,23.5 20.32,23.5 15.88,27.94 8.89,27.94 v6.35,25.4
VCC  (via drill 0.51)
  Top 0.254: 9.53,62.87 C12.1 v9.53,60.96 | v9.53,60.96 9.53,61.59 | 17.06,37.23 17.14,37.15 17.14,36.2 17.71,35.63 U1.6 | R5.1 v34.29,44.45 45.72,44.45 | 45.72,44.45 45.72,45.72 | U5.3 44.45,27.3 41.27,27.3 40.62,26.66 C10.2 39.37,26.67 38.73,26.04 38.73,25.4 | 43.81,25.4 U5.4 40.64,25.4 40.01,24.77 C11.1 39.35,24.14 38.73,24.77 38.73,25.4 | v36.83,25.4 38.73,25.4 | 29.84,23.5 v29.84,25.4 29.84,30.48 | 29.84,30.48 29.84,32.37 C1.1 29.21,32.38 28.57,33.02 28.57,34.29 28.04,34.83 U1.18 | 17.06,37.23 U1.4 | 29.84,23.5 26.67,23.5 | 26.67,23.5 JP3.2 | 26.67,23.5 25.4,23.5 | 25.4,23.5 24.13,23.5 23.5,22.86 21.59,22.86 | 21.59,22.86 18.41,22.86 17.78,23.5 14.61,23.5 13.34,24.77 13.34,36.83 13.96,37.45 C2.1 16.84,37.45 17.06,37.23 | JP6-DNP.1 8.37,62.87 9.53,62.87 | 29.84,30.48 33.02,30.48 34.29,31.75 v34.29,40.64 33.66,41.27 R4.1 32.38,41.27 | R1.2 v15.88,3.81 | 29.84,23.5 29.84,12.8 31.85,10.79 39.37,10.79 | 39.37,10.79 U4.4 | v9.53,60.96 8.89,60.33 8.89,55.37 D9.1 | 26.04,54.61 26.04,53.34 25.4,52.7 R17.1 | 39.37,10.79 C9.1 | 26.04,54.61 D7.1 | D5.1 46.23,52.59 45.72,52.07 45.72,45.72 | 45.72,44.45 45.72,40.64 | 18.93,63.5 D11.1 | 18.93,63.5 25.4,63.5 26.04,62.87 26.04,54.61 | 9.53,62.87 10.79,62.87 11.43,63.5 18.93,63.5 | 45.72,45.72 JP7.5 | 45.72,40.64 JP7.3 | 45.72,40.64 R8.1 | U2.5 23.18,20.64 23.5,20.95 C7.A 25.4,20.95 25.4,23.5 | R3.2 21.61,22.88 21.59,22.86
  Bottom 0.254: v9.53,60.96 9.53,45.72 8.26,44.45 4.45,44.45 1.91,41.91 1.91,30.48 3.17,29.21 5.08,29.21 6.35,30.48 15.24,30.48 20.95,24.77 24.77,24.77 JP3.2 | JP6-DNP.1 2.54,60.21 JP8.1 | v15.88,3.81 17.78,3.81 29.84,15.88 v29.84,25.4 v36.83,25.4 | v34.29,40.64 v34.29,44.45
VRAW  (via drill 0.51)
  Top 0.254: v3.81,30.48 S1.2 6.99,30.48 7.62,29.84 7.62,27.3 9.53,25.4 11.75,25.4 15.88,21.27 C5.1 | C5.1 16.51,21.27 | C5.1 17.48,21.26 18.1,20.64 U2.1 | U2.3 16.82,18.73 16.51,19.05 C5.1
  Bottom 0.254: JP5-DNP.2 10.79,43.81 5.08,43.81 2.54,41.27 2.54,31.75 v3.81,30.48
VUSB
  Top 0.254: 6.03,27.98 S1.1 6.07,27.59 8.89,24.77 11.43,24.77 13.02,23.18 13.02,18.73 11.1,16.82 11.1,13.03 | U3.20 16.8,7.33 11.1,13.03 | JP4.VBUS 11.1,13.03
WDIR  (via drill 0.51)
  Top 0.254: v27.94,41.27 28.57,40.64 28.57,39.37 28.04,38.83 U1.23 | v26.04,50.8 24.13,50.8 23.48,51.45 R17.2 23.48,53.48 22.98,53.98 D7.2 22.98,55.37 23.18,55.56 23.81,55.56 25.08,55.56 25.28,55.76 D8.1 | D8.1 25.28,57.27 24.78,57.77 R13.1 | D8.1 25.4,56.52
  Bottom 0.254: v26.04,50.8 26.68,50.16 26.68,42.54 v27.94,41.27
WSPEED
  Top 0.254: U1.1 18.57,42.39 17.14,43.81 13.97,43.81 13.02,42.86 13.02,41.59 12.06,40.64 11.43,40.64 9.84,39.05 7.94,39.05 6.35,40.64 5.08,40.64 4.45,41.27 4.45,43.81 5.08,44.45 7.62,44.45 8.89,45.72 8.89,51.56 D9.2 | R14.1 10.14,57.77 9.64,57.27 D10.1 9.64,55.76 9.84,55.56 11.75,55.56 11.95,55.37 D9.2 | D9.2 11.94,54.61
XCLR  (via drill 0.51)
  Top 0.254: v49.85,25.4 U5.8 | U1.13 23.26,33.42 24.13,34.29 24.77,34.92 v25.4,34.92
  Bottom 0.254: v25.4,34.92 34.29,34.92 34.92,34.29 34.92,30.48 40.01,25.4 v49.85,25.4

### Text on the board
Bottom: 4-13-11
tPlace: Wind | Rain | XBee | BlueSMiRF | RF | Comm | USB | Light | BAT | Power | USB | + | 3.7-12V | RST | ISP | Pressure | - | Humidity | Status | Power | USB Weather V3
bPlace: 1 | 20 | 3.3V | 5 | 2 | GND | WIND | RAIN | SCL | SDA | 10 | 11 | CTS | VRAW | GND | RX-I | TX-O | BT-RTS | 3.3V | GND | 3.3V | GND | LIGHT | RST | SCK | MISO | GND | MOSI | 3.3V | BAT | GND
tValues: DNP | DNP | DNP | SMD Button | USB Weather Board v3 | R. Owens, M. Grusin
Document: 0.00" | 0.10" | 0.70" | 1.50" | 1.90" | 2.00" | 2.60" | 2.50" | 0.85" | 0.45" | 0.10" | 0.00"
